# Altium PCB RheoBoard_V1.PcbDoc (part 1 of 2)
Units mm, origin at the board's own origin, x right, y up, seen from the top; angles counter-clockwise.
Board outline 146 x 88.34 mm, 2 copper layers (Top Layer, Bottom Layer); 132 components, 71 nets, 340 pads, 144 vias.
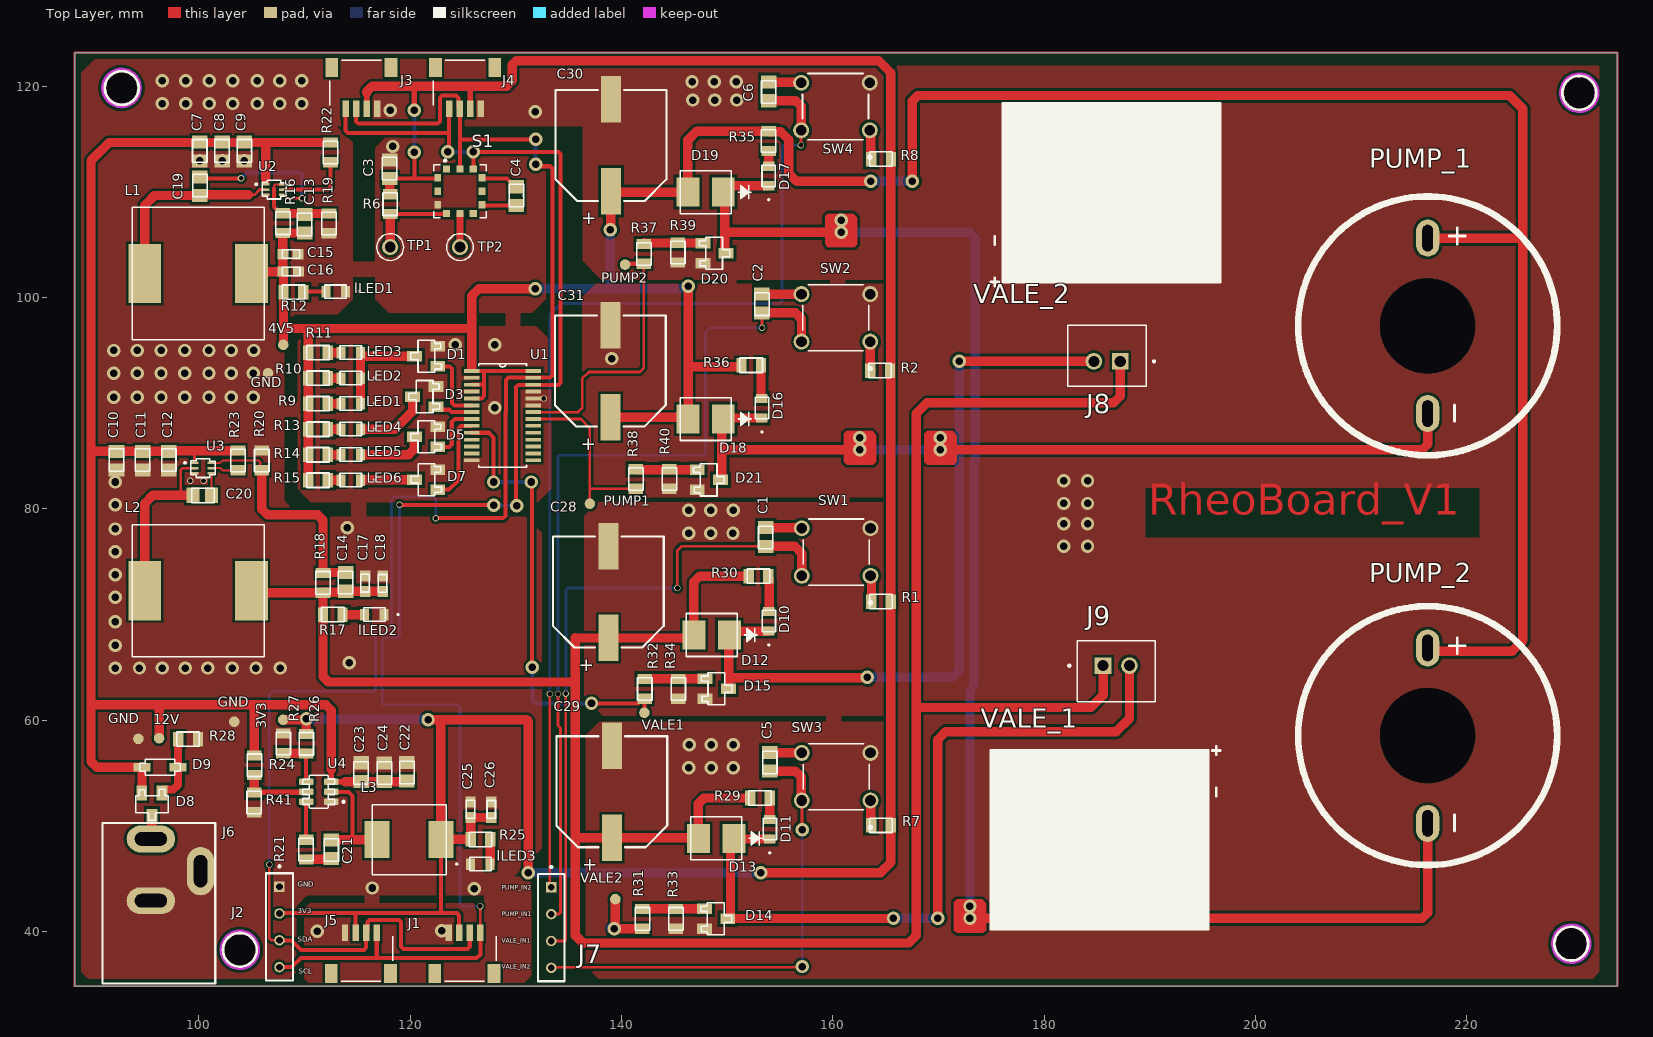
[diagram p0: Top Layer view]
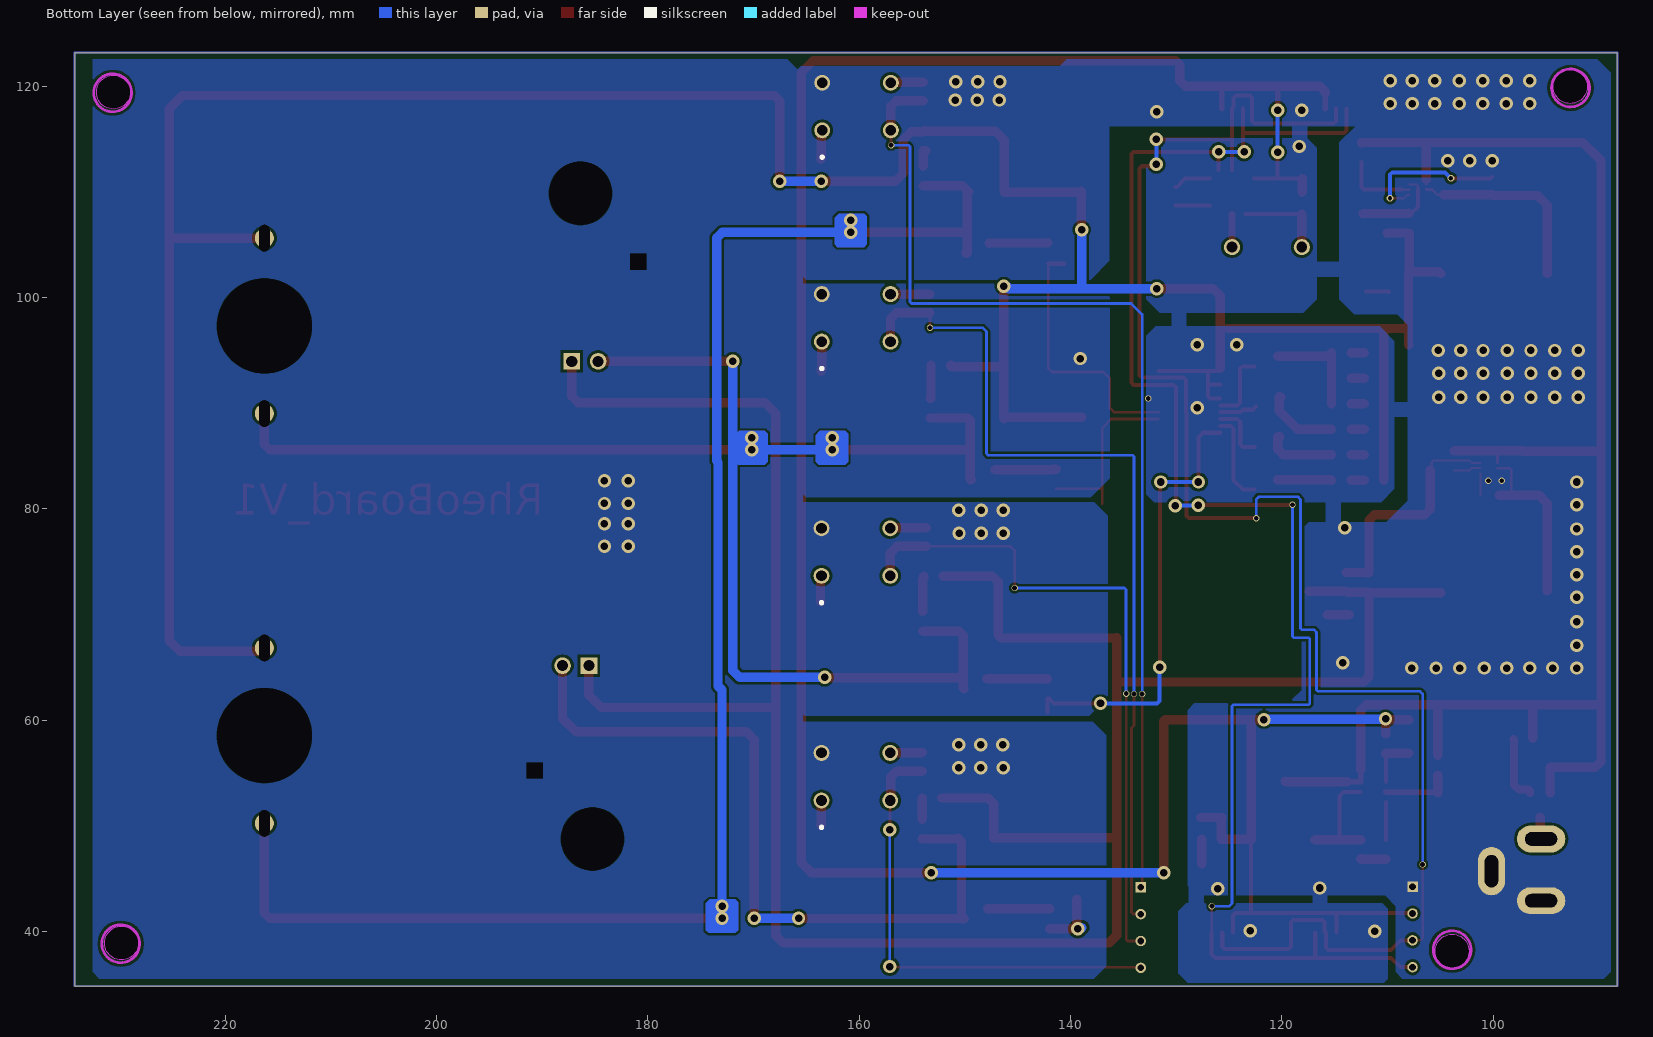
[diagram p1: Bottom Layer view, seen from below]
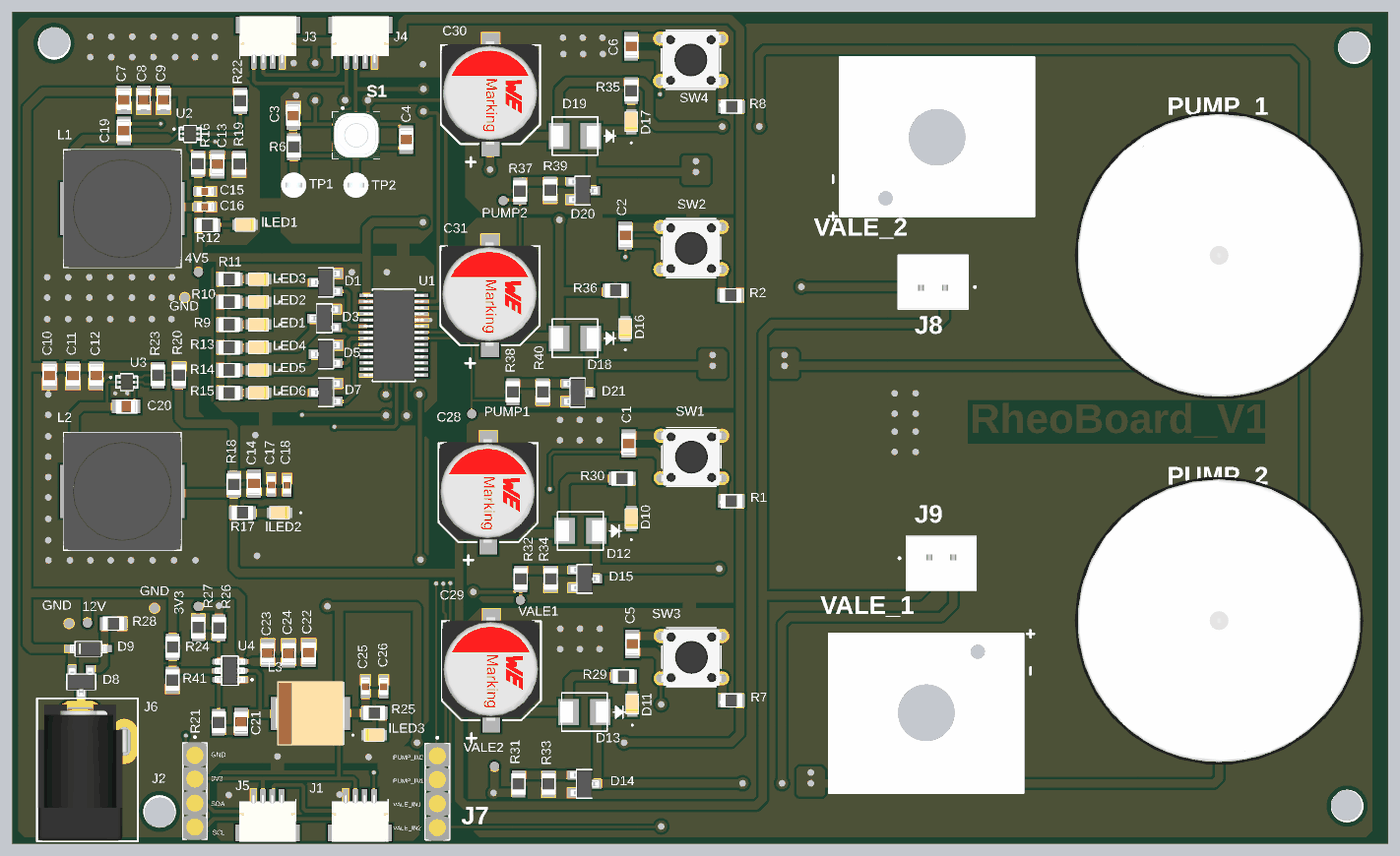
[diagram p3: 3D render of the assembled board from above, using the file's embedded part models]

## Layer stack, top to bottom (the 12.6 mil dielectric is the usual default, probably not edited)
Top Solder: solder mask 0.0102, Solder Resist, Dk 3.5
Top Layer: signal copper 0.0356
Dielectric 1: dielectric 0.32, FR-4, Dk 4.8
Bottom Layer: signal copper 0.0356
Bottom Solder: solder mask 0.0102, Solder Resist, Dk 3.5

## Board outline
88.24,34.85 88.24,123.19 106.965,123.19 234.244,123.19 234.244,34.85
cut-out: 228.201,38.92 ccw(c229.801,38.92) 229.801,37.32 ccw(c229.801,38.92) 231.401,38.92 ccw(c229.801,38.92) 229.801,40.52 ccw(c229.801,38.92)
cut-out: 228.201,38.92 ccw(c229.801,38.92) 229.801,37.32 ccw(c229.801,38.92) 231.401,38.92 ccw(c229.801,38.92) 229.801,40.52 ccw(c229.801,38.92)
cut-out: 228.963,119.438 ccw(c230.563,119.438) 230.563,117.838 ccw(c230.563,119.438) 232.163,119.438 ccw(c230.563,119.438) 230.563,121.038 ccw(c230.563,119.438)
cut-out: 228.963,119.438 ccw(c230.563,119.438) 230.563,117.838 ccw(c230.563,119.438) 232.163,119.438 ccw(c230.563,119.438) 230.563,121.038 ccw(c230.563,119.438)
cut-out: 91.11,119.957 ccw(c92.71,119.957) 92.71,118.357 ccw(c92.71,119.957) 94.31,119.957 ccw(c92.71,119.957) 92.71,121.557 ccw(c92.71,119.957)
cut-out: 102.286,38.158 ccw(c103.886,38.158) 103.886,36.558 ccw(c103.886,38.158) 105.486,38.158 ccw(c103.886,38.158) 103.886,39.758 ccw(c103.886,38.158)

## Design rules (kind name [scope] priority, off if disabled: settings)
Clearance [All] p1: gap=0.254 ignorepadtopadclearanceinfootprint=FALSE except(0: Arc-Hole Track-Hole SMDPad-Hole THPad-Hole Via-Hole Fill-Hole Poly-Hole Region-Hole Text-Hole)
PolygonConnect [All] p1: connectstyle=Direct reliefconductorwidth=0.254 reliefentries=4 polygonreliefangle="90 Angle" airgapwidth=0.254
RoutingVias [All] p1: holewidth=0.45 width=0.55 viastyle="Through Hole" minholewidth=0.381 minwidth=0.381 maxholewidth=1.27 maxwidth=1.27
SolderMaskExpansion [All] p1: expansion=0.102 istentingtop=FALSE
Width [All] p1: maxlimit=0.889 minlimit=0.203 preferedwidth=0.381 minimp=50.000000 maximp=50.000000 favimp=50.000000
30 further rules are at their usual default settings.

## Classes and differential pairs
component class POWER: 3V3 4V5 12V C7 C8 C9 C10 C11 C12 C13 C14 C15 C16 C17 C18 C19 C20 C21 C22 C23 C24 C25 C26 D8 D9 GND J6 L1 L2 L3 lLED1 lLED2 lLED3 R12 R16 R17 R18 R19 R20 R21 R22 R23 R24 R25 R26 R27 R28 R41 U2 U3 U4
component class MAIN: C1 C2 C3 C4 C5 C6 C28 C29 C30 C31 D1 D3 D5 D7 D10 D11 D12 D13 D14 D15 D16 D17 D18 D19 D20 D21 J1 J2 J3 J4 J5 J7 J8 J9 LED1 LED2 LED3 LED4 LED5 LED6 PUMP1 PUMP2 PUMP_1 PUMP_2 R1 R2 R6 R7 R8 R9 R10 R11 R13 R14 R15 R29 R30 R31 R32 R33 R34 R35 R36 R37 R38 R39 R40 S1 SW1 SW2 SW3 SW4 TP1 TP2 U1 VALE1 VALE2 VALE_1 VALE_2

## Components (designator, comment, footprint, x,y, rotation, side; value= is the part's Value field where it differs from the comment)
3V3 "TP_1MM" TP_1mm 107.975,60.046 r90 top
4V5 "TP_1MM" TP_1mm 108.001,95.529 r90 top
12V "TP_1MM" TP_1mm 96.241,58.293 r90 top
C1 "0.1UF,50V" CAP_CER_0805 153.64,77.35 r270 top
C2 "0.1UF,50V" CAP_CER_0805 153.289,99.441 r270 top
C3 "0.1UF,50V" CAP_CER_0805 118.06,112.15 r90 top
C4 "1nF 50V" CAP_CER_0805 130.048,109.601 r90 top
C5 "0.1UF,50V" CAP_CER_0805 154.035,56.07 r270 top
C6 "0.1UF,50V" CAP_CER_0805 153.924,119.507 r270 top
C7 "10UF 50V" CAP_CER_0805 100.09,113.824 r90 top
C8 "10UF 50V" CAP_CER_0805 102.2,113.824 r90 top
C9 "0.1UF,50V" CAP_CER_0805 104.31,113.824 r90 top
C10 "10UF 50V" CAP_CER_0805 92.212,84.564 r90 top
C11 "10UF 50V" CAP_CER_0805 94.688,84.564 r90 top
C12 "0.1UF,50V" CAP_CER_0805 97.165,84.564 r90 top
C13 "18pF 50V" CAP_CER_0805 110.01,106.99 r270 top
C14 "18pF 50V" CAP_CER_0805 113.896,73.1 r270 top
C15 "22uF 6.3V" CAP_CER_0603 108.68,104.11 r180 top
C16 "22uF 6.3V" CAP_CER_0603 108.69,102.46 r180 top
C17 "22uF 6.3V" CAP_CER_0603 115.74,72.93 r270 top
C18 "22uF 6.3V" CAP_CER_0603 117.4,72.91 r270 top
C19 "0.1UF,50V" CAP_CER_0805 100.1,110.54 r90 top
C20 "0.1UF,50V" CAP_CER_0805 100.33,81.28 r0 top
C21 "0.1UF,50V" CAP_CER_0805 112.54,47.8 r270 top
C22 "0.1UF,50V" CAP_CER_0805 119.699,55.136 r270 top
C23 "10UF 25V" CAP_CER_0805 115.36,55.095 r270 top
C24 "10UF 25V" CAP_CER_0805 117.569,55.076 r270 top
C25 "22uF 6.3V" CAP_CER_0603 125.72,51.53 r270 top
C26 "22uF 6.3V" CAP_CER_0603 127.671,51.525 r270 top
C28 "100uF 25V" CAP_ALUM_SMD_D10_H12.4 138.75,72.14 r270 top
C29 "100uF 25V" CAP_ALUM_SMD_D10_H12.4 139.08,53.24 r270 top
C30 "100uF 25V" CAP_ALUM_SMD_D10_H12.4 139,114.395 r270 top
C31 "100uF 25V" CAP_ALUM_SMD_D10_H12.4 138.94,93.04 r270 top
D1 "30V 5.8A" SOT-23-3 121.505,94.445 r90 top
D3 "30V 5.8A" SOT-23-3 121.335,90.635 r90 top
D5 "30V 5.8A" SOT-23-3 121.505,86.825 r90 top
D7 "30V 5.8A" SOT-23-3 121.51,82.77 r90 top
D8 "20V 4A" SOT-23-3 95.57,52.02 r180 top
D9 "BZT52C5V1" SOD-123 96.33,55.56 r0 top
D10 "Led green" "LED_LS R976_AOS" 153.94,69.38 r90 top
D11 "Led green" "LED_LS R976_AOS" 154.03,49.7 r90 top
D12 "3A 40V" DO214AA 148.53,68.07 r180 top
D13 "3A 40V" DO214AA 148.955,48.835 r180 top
D14 "30V 5.8A" SOT-23-3 148.955,41.215 r270 top
D15 "30V 5.8A" SOT-23-3 149.01,62.99 r270 top
D16 "Led green" "LED_LS R976_AOS" 153.289,89.535 r90 top
D17 "Led green" "LED_LS R976_AOS" 153.924,111.506 r90 top
D18 "3A 40V" DO214AA 147.954,88.508 r180 top
D19 "3A 40V" DO214AA 147.954,109.982 r180 top
D20 "30V 5.8A" SOT-23-3 148.798,104.196 r270 top
D21 "30V 5.8A" SOT-23-3 148.273,82.748 r270 top
GND "TP_1MM" TP_1mm 103.353,59.868 r90 top
GND "TP_1MM" TP_1mm 94.285,58.242 r90 top
GND "TP_1MM" TP_1mm 106.553,92.837 r90 top
J1 "14417" SPARKFUN_PRT-14417 125.14,37.453 r0 top
J2 "TS-104-T-A" HDR_THT_1X04_P2.54 107.63,40.45 r270 top
J3 "14417" SPARKFUN_PRT-14417 115.39,120.33 r180 top
J4 "14417" SPARKFUN_PRT-14417 125.19,120.33 r180 top
J5 "14417" SPARKFUN_PRT-14417 115.34,37.453 r0 top
J6 "694106301002" "CONN PWR JACK 2.1X5.5MM SOLDER" 95.72,42.93 r90 top
J7 "TS-104-T-A" HDR_THT_1x04_P2.54 133.35,40.386 r270 top
J8 "VERT" CONN_SMD_TOP_P2.50 185.941,94.488 r0 top
J9 "VERT" CONN_SMD_TOP_P2.50 186.817,64.643 r180 top
L1 "2.2uH" IND_12.5x12.5_H8.5 99.93,102.28 r180 top
L2 "2.2uH" IND_12.5x12.5_H8.5 99.93,72.263 r180 top
L3 "4.7uH" IND_6.8X6.5_H2.8 123.42,52 r180 top
LED1 "RED 2V 20mA" "LED_LS R976_AOS" 114.381,89.965 r180 top
LED2 "RED 2V 20mA" "LED_LS R976_AOS" 114.381,92.378 r180 top
LED3 "RED 2V 20mA" "LED_LS R976_AOS" 114.381,94.791 r180 top
LED4 "Led green" "LED_LS R976_AOS" 114.381,87.552 r180 top
LED5 "Led green" "LED_LS R976_AOS" 114.381,85.139 r180 top
LED6 "Led green" "LED_LS R976_AOS" 114.381,82.726 r180 top
lLED1 "RED 2V 20mA" "LED_LS R976_AOS" 112.95,100.56 r180 top
lLED2 "RED 2V 20mA" "LED_LS R976_AOS" 116.62,70 r180 top
lLED3 "RED 2V 20mA" "LED_LS R976_AOS" 126.65,46.4 r0 top
PUMP1 "TP_1MM" TP_1mm 137.008,80.493 r90 top
PUMP2 "TP_1MM" TP_1mm 140.335,103.124 r90 top
PUMP_1 "0010844022" "PUMP_LPM - ZR370-02PM" 216.281,97.327 r270 top
PUMP_2 "0010844022" "PUMP_LPM - ZR370-02PM" 216.281,58.547 r270 top
R1 "10K 1% 0805" RES_0805 164.55,71.23 r0 top
R2 "10K 1% 0805" RES_0805 164.465,93.091 r0 top
R6 "10K 1% 0805" RES_0805 118.11,108.839 r90 top
R7 "10K 1% 0805" RES_0805 164.55,50.07 r0 top
R8 "10K 1% 0805" RES_0805 164.564,113.106 r0 top
R9 "220R 0805" RES_0805 111.279,89.959 r180 top
R10 "220R 0805" RES_0805 111.279,92.372 r180 top
R11 "220R 0805" RES_0805 111.279,94.785 r180 top
R12 "1K 1% 0805" RES_0805 108.95,100.51 r180 top
R13 "220R 0805" RES_0805 111.279,87.546 r0 top
R14 "220R 0805" RES_0805 111.279,85.133 r0 top
R15 "220R 0805" RES_0805 111.279,82.72 r0 top
R16 "130K 0805" RES_0805 107.96,107.04 r270 top
R17 "1K 1% 0805" RES_0805 112.68,70 r180 top
R18 "270K 0805" RES_0805 111.754,73.01 r270 top
R19 "20K 0805" RES_0805 112.32,107.02 r270 top
R20 "30K 0805" RES_0805 105.96,84.6 r270 top
R21 "30Ohm 0805" RES_0805 110.15,47.76 r270 top
R22 "100K 0805" RES_0805 112.46,113.74 r90 top
R23 "100K 0805" RES_0805 103.71,84.6 r90 top
R24 "174K 0805" RES_0805 105.26,55.75 r90 top
R25 "470R 0805" RES_0805 126.655,48.731 r180 top
R26 "75K 0805" RES_0805 110.169,57.779 r90 top
R27 "24K 0805" RES_0805 108,57.81 r270 top
R28 "100K 0805" RES_0805 98.99,58.21 r180 top
R29 "220R 0805" RES_0805 153.105,52.645 r0 top
R30 "220R 0805" RES_0805 152.96,73.64 r0 top
R31 "100R 0805" RES_0805 141.97,41.215 r90 top
R32 "100R 0805" RES_0805 142.195,62.97 r90 top
R33 "10K 1% 0805" RES_0805 145.145,41.215 r90 top
R34 "10K 1% 0805" RES_0805 145.37,62.97 r90 top
R35 "220R 0805" RES_0805 153.924,114.808 r270 top
R36 "220R 0805" RES_0805 152.273,93.599 r0 top
R37 "100R 0805" RES_0805 142.113,104.14 r90 top
R38 "100R 0805" RES_0805 141.361,82.831 r90 top
R39 "10K 1% 0805" RES_0805 145.322,104.25 r90 top
R40 "10K 1% 0805" RES_0805 144.536,82.831 r90 top
R41 "36.5K 0805" RES_0805 105.239,52.233 r90 top
S1 "MPRLS0025PA00001A" XDCR_MPRLS0025PA00001A 124.714,110.061 r0 top
SW1 "B3F-1020" SW_B3F-1000_OMR 163.56,73.67 r180 top
SW2 "B3F-1020" SW_B3F-1000_OMR 163.531,95.832 r180 top
SW3 "B3F-1020" SW_B3F-1000_OMR 163.56,52.415 r180 top
SW4 "B3F-1020" SW_B3F-1000_OMR 163.498,115.826 r180 top
TP1 "5002" KEYSTONE_5002 118.11,104.775 r0 top
TP2 "5002" KEYSTONE_5002 124.714,104.775 r0 top
U1 "PCA9685PW,118" TSSOP-28 128.745,88.835 r0 top
U2 "TPS563203DRLR" SOT-563 107.13,110.22 r0 top
U3 "TPS563203DRLR" SOT-563 100.4,83.86 r0 top
U4 "TPS56339DDCT" SOT-23-6 111.35,53.235 r180 top
VALE1 "TP_1MM" TP_1mm 142.164,60.719 r90 top
VALE2 "TP_1MM" TP_1mm 139.421,43.078 r90 top
VALE_1 "0010844022" VALE_FA0520E 185.226,48.768 r270 top
VALE_2 "0010844022" VALE_FA0520E 186.369,109.855 r90 top

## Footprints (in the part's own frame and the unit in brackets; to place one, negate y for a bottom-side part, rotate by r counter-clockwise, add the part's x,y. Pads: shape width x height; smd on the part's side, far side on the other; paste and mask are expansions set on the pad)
CAP_ALUM_SMD_D10_H12.4 [mm]
  rect 4.4x1.9 smd: 1(4.35,0) 2(-4.35,0)
  silkscreen extent -5.25,-5.25 5.25,5.25, body extent -5.67,-5.21 5.33,5.09, height 12.25
CAP_CER_0603 [mm]
  rect 1.04x0.97 smd paste+0 mask+0.102: 1(-0.726,0) 2(0.726,0)
  silkscreen extent -0.89,-0.4 0.79,0.4, body extent -0.8,-0.4 0.8,0.4, height 0.95
CAP_CER_0805 [mm]
  rect 1.24x1.47 smd: 1(-0.885,0) 2(0.885,0)
  silkscreen extent -1,-0.68 1.13,0.68, body extent -1,-0.62 1,0.63, height 1.45
"CONN PWR JACK 2.1X5.5MM SOLDER" [mil]
  oval 100x180 hole 50 slot 120 at 90 deg: 1(230,10) 2(0,10)
  oval 180x100 hole 50 slot 120 at 0 deg: 3(110,-175)
  silkscreen extent -308,-230 290,190, body extent -306,-187 265,187, height 421
CONN_SMD_TOP_P2.50 [mm]
  rect 1.575x1.575 / inner round 1.575 / far side rect 1.575x1.575 hole 1.05: 1(1.25,-0.525)
  round 1.575 hole 1.05: 2(-1.25,-0.525)
  silkscreen extent -3.7,-2.88 4.54,2.88, body extent -3.75,-2.79 3.75,2.91, height 2.11
DO214AA [mil]
  rect 85x108 smd paste+0 mask+0: 1(-66,0) 2(66,0)
  silkscreen extent -170,-80 95,80, body extent -108,-78 108,78, height 96
HDR_THT_1X04_P2.54 [mm]
  rect 0.985x0.985 hole 0.635: 01(-3.81,0)
  round 0.985 hole 0.635: 02(-1.27,0) 03(1.27,0) 04(3.81,0)
  silkscreen extent -5.83,-1.27 5.08,1.27, body extent -5.18,-1.27 5.18,1.27, height 8.28
HDR_THT_1x04_P2.54 [mm]
  rect 0.985x0.985 hole 0.635: 01(-3.81,0)
  round 0.985 hole 0.635: 02(-1.27,0) 03(1.27,0) 04(3.81,0)
  silkscreen extent -5.83,-1.27 5.08,1.27, body extent -5.18,-1.27 5.18,1.27, height 8.28
IND_6.8X6.5_H2.8 [mm]
  rect 2.35x3.5 smd: 1(6.55,3.3) 2(0.5,3.3)
  silkscreen extent 0,0 7,6.6, body extent -0.09,-0.1 7.2,6.71, height 3.05
IND_12.5x12.5_H8.5 [mm]
  rect 3.1x5.6 smd: 1(-5.05,0) 2(5.05,0)
  silkscreen extent -6.25,-6.25 6.25,6.25, body extent -6.25,-6.25 6.25,6.25, height 6.5
KEYSTONE_5002 [mm]
  round 1.53 hole 1.02: TP(0,0)
  silkscreen extent -1.27,-1.27 1.27,1.27, body extent -1.27,-1.27 1.27,1.27, height 4.57
"LED_LS R976_AOS" [mil]
  rect 33.78x43 smd paste+0 mask+0: 1(-36.39,0) 2(36.39,0)
  silkscreen extent -91,-25 40,25, body extent -39,-26 39,26, height 32
"PUMP_LPM - ZR370-02PM" [mm]
  oval 3.5x2.2 / inner round 1.524 / far side round 1.808 hole 1 slot 2.5 at 0 deg paste-2539.97 mask+0: 1(-8.3,0) 2(8.3,0)
  round 1.524 hole 9 unplated: 3(0,0)
  silkscreen extent -12.25,-12.25 12.25,12.25, body extent -15.31,-15.31 15.31,15.31, height 65
RES_0805 [mm]
  rect 0.97x1.38 smd: 1(-0.93,0) 2(0.93,0)
  silkscreen extent -1.07,-0.69 1.07,0.68, body extent -1,-0.62 1,0.63, height 0.6
SOD-123 [mm]
  rect 1.6x0.8 smd: 1(-1.7,0) 2(1.7,0)
  silkscreen extent -1.91,-0.76 1.91,0.76, body extent -1.82,-0.77 1.83,0.78, height 1.44
SOT-23-3 [mm]
  rect 1x1.4 smd paste+0 mask+0.102: 1(-0.95,-1.1) 2(0.95,-1.1) 3(0,1.1)
  silkscreen extent -1.52,-1.46 1.52,1.46, body extent -1.45,-1.4 1.45,1.4, height 1.25
SOT-23-6 [mm]
  rrect25% 1.35x0.6 smd: 1(-1.185,0.95) 2(-1.185,0) 3(-1.185,-0.95) 4(1.185,-0.95) 5(1.185,0) 6(1.185,0.95)
  silkscreen extent -2.45,-1.55 1.52,1.55, body extent -1.4,-1.5 1.4,1.5, height 1.16
SOT-563 [mil]
  rect 28x9 smd paste+0 mask+0: 1(-31.5,19.69) 2(-31.5,0) 3(-31.5,-19.69) 4(31.5,-19.69) 5(31.5,0) 6(31.5,19.69)
  silkscreen extent -71,-35 45,35, body extent -34,-34 34,34, height 24
SPARKFUN_PRT-14417 [mm]
  rect 0.6x1.55 smd: 1(-1.5,2.45) 2(-0.5,2.45) 3(0.5,2.45) 4(1.5,2.45)
  rect 1.2x1.8 smd: S1(-2.8,-1.425) S2(2.8,-1.425)
  silkscreen extent -1.88,-2.12 3,2.12, body extent -3,-2.37 3,2.58, height 2.95
SW_B3F-1000_OMR [mm]
  round 1.508 / inner round 1.524 / far side round 1.508 hole 1 paste-2539.97 mask+0: 1(0,0) 2(6.5,0) 3(0,-4.5) 4(6.5,-4.5)
  silkscreen extent -0.13,-5.38 6.38,2.67, body extent -0.7,-5.24 7.2,0.76, height 5
TP_1mm [mm]
  round 1 smd: 1(0,0)
TSSOP-28 [mil]
  rect 58x14 smd: 1(-115,166) 2(-115,141) 3(-115,115) 4(-115,90) 5(-115,64) 6(-115,38) 7(-115,13) 8(-115,-13) 9(-115,-38) 10(-115,-64) 11(-115,-90) 12(-115,-115) 13(-115,-141) 14(-115,-166) 15(115,-166) 16(115,-141) 17(115,-115) 18(115,-90) 19(115,-64) 20(115,-38) 21(115,-13) 22(115,13) 23(115,38) 24(115,64) 25(115,90) 26(115,115) 27(115,141) 28(115,166)
  silkscreen extent -89,-193 89,193, body extent -126,-191 126,191, height 43
VALE_FA0520E [mm]
  rect 1x0.8 hole 1.5 square unplated: 4(-6.477,5.461)
  rect 1.5x0.8 hole 6 unplated: 4(0,0)
  silkscreen extent -8.76,-10.29 8.51,11.43, body extent -8.1,-10 18,10, height 55.19
XDCR_MPRLS0025PA00001A [mm]
  rect 0.7x0.65 smd: 1(-1.27,2.1) 2(0,2.1) 3(1.27,2.1) 7(1.27,-2.1) 8(0,-2.1) 9(-1.27,-2.1)
  rect 0.65x0.7 smd: 4(2.1,1.27) 5(2.1,0) 6(2.1,-1.27) 10(-2.1,-1.27) 11(-2.1,0) 12(-2.1,1.27)
  silkscreen extent -2.5,-2.5 2.5,3, body extent -2.46,-2.5 2.54,2.5, height 5.9

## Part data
C1 C2 C3 C5 C6 C9 C12 C19 C20 C21 C22: library part "CAP_CER, 0805, X7R, 0.1UF, 5%, 50V", "Ceramic Capacitor, Multilayer, Ceramic, 50V, 10% +Tol, 10% -Tol, X7R, 15% TC, 0.1uF, Surface Mount, 0805", Capacitance=100nF, Dielectric Material=Ceramic, Manufacturer=Nextgen, Manufacturer Part Number=0805B104K500BD, Max Operating Temperature=125°C, Min Operating Temperature=-55°C, Supplier Part Number 1=3372-0805B104K500BDTR-ND, Voltage Rating (DC)=50V
C4: library part "CAP_CER 0805 1NF 50V ULTRA STABL", "Cap Ceramic 0.001uF 50V X8R 10% Pad SMD 0805 150C T/R Automotive AEC-Q200", Capacitance=1nF, Case/Package=0805, Dielectric=X8R, Dielectric Material=Ceramic, Manufacturer="Yageo Group", Manufacturer Part Number=C0805C102K5HACAUTO, Max Operating Temperature=150°C, Min Operating Temperature=-55°C, Ratings=AEC-Q200, Supplier Part Number 1=399-C0805C102K5HACAUTODKR-ND, Temperature Coefficient=30ppm/°C, Voltage Rating=50V
C7 C8 C10 C11: library part "CAP_CER, 0805, X5R, 10UF, 10%, 50V", "CAP_CER,0805,X5R,10UF,10%,50V", Manufacturer=Nextgen, Manufacturer Part Number=0805W106K500CC, Supplier Part Number 1=3372-0805W106K500CCTR-ND
C13 C14: library part "CAP_CER, 18PF 50V X8R 0805", "Multilayer Ceramic Capacitors MLCC - SMD/SMT 50V 18pF X8R 0805 5%", Capacitance=18pF, Case/Package=0805, Dielectric=X8R, Dielectric Material=Ceramic, Manufacturer="Yageo Group", Manufacturer Part Number=C0805C180J5HACTU, Max Operating Temperature=150°C, Min Operating Temperature=-55°C, Supplier Part Number 1=399-C0805C180J5HACTUCT-ND, Temperature Coefficient=30ppm/°C, Voltage Rating=50V
C15 C16 C17 C18 C25 C26: library part "CAP_CER 22UF 6.3V X6S 0603", "6.3V 22uF X6S ±20% 0603 Multilayer Ceramic Capacitors MLCC - SMD/SMT ROHS", Capacitance=22µF, Case Code (Imperial)=0603, Case Code (Metric)=1608, Dielectric=X6S, Dielectric Material=Ceramic, Manufacturer=Murata, Manufacturer Lifecycle Status="IN PRODUCTION", Manufacturer Part Number=GRM188C80J226ME15D, Max Operating Temperature=105°C, Min Operating Temperature=-55°C, Supplier Part Number 1=490-10471-1-ND, Tolerance=20%, Voltage Rating=6.3V
C23 C24: library part "CAP_CER, 0805, X5R, 10UF, 10%, 25V", "Cap SMD, 0805, X5R, 10UF, 10%, 25V", Manufacturer=Nextgen, Manufacturer Part Number=0805W106K250CC, Supplier Part Number 1=3372-0805W106K250CCTR-ND
C28 C29 C30 C31: library part "CAP ALUM POLY 100UF 20% 25V SMD", "WCAP-PSLC Aluminum Polymer Capacitors", Capacitance=100µF, Case/Package=Radial, ESR (Equivalent Series Resistance)=15mΩ, Leakage Current=500µA, Manufacturer="Wurth Elektronik", Manufacturer Lifecycle Status=ACTIVE, Manufacturer Part Number=875075561005, Max Operating Temperature=105°C, Min Operating Temperature=-55°C, Ripple Current=4.8A, Supplier Part Number 1=732-6499-6-ND, Tolerance=20%, Voltage Rating=25V
D1 D3 D5 D7 D14 D15 D20 D21: library part "MOSFET N-CH 30V 5.8A SOT23-3", "Trans MOSFET N-CH 30V 5.7A 3-Pin SOT-23", Case/Package=SOT-23, Continuous Drain Current (ID)=5.7A, Drain to Source Breakdown Voltage=30V, Drain to Source Resistance=26.5mΩ, Gate to Source Voltage (Vgs)=12V, Input Capacitance=630pF, Manufacturer="Alpha & Omega Semiconductor", Manufacturer Part Number=AO3400A, Max Junction Temperature (Tj)=150°C, Max Power Dissipation=1.4W, Min Operating Temperature=-55°C, Supplier Part Number 1=785-1000-2-ND, Threshold Voltage=650mV
D8: library part "MOSFET P-CH 20V 4A SOT23-3", "P-ch Mosfet 20V 4A 39MΩ@4A, 4.5V 9.1NC@4.5V 294PF@10V SOT-23-3 SMD 2.9MM × 1.3MM × 1.03MM", Case/Package=SOT-23, Continuous Drain Current (ID)=4A, Drain to Source Breakdown Voltage=-20V, Drain to Source Resistance=42.5mΩ, Gate to Source Voltage (Vgs)=8V, Input Capacitance=294pF, Manufacturer="Diodes Inc.", Manufacturer Part Number=DMG3415U-7, Max Junction Temperature (Tj)=150°C, Max Power Dissipation=900mW, Min Breakdown Voltage=20V, Min Operating Temperature=-55°C, Supplier Part Number 1=DMG3415UDIDKR-ND, Threshold Voltage=-550mV
D9: library part "DIODE ZENER 5.1V 500MW SOD123F", "BZT52C5V1 Series 500 mW 5.1 V 10 mA Surface Mount Zener Diode - SOD-123", Current=1A, Forward Current=10mA, Forward Voltage=900mV, Manufacturer="Diodes Inc.", Manufacturer Part Number=BZT52C5V1-7-F, Max Junction Temperature (Tj)=150°C, Max Power Dissipation=370mW, Max Reverse Leakage Current=2µA, Min Operating Temperature=-65°C, Output Current=50mA, Power Rating=500mW, Reference Voltage=5.1V, Reverse Standoff Voltage=2V, Supplier Part Number 1=BZT52C5V1-FDICT-ND, Test Current=5mA, Tolerance=6%, Voltage Tolerance=5.88%
D10 D11 D16 D17 LED4 LED5 LED6: library part "LED GREEN CLEAR CHIP SMD", "Single-color LEDs; LITEON; LTST-C190GKT; Green; 130 °; 2.1 V; 0603", Case Code (Imperial)=0603, Case Code (Metric)=1608, Color=Green, Current=1A, Forward Current=30mA, Forward Voltage=2.6V, Lens Color="Clear, Colorless", Manufacturer="Diodes Inc.", Manufacturer Part Number=LTST-C190GKT, Max Operating Temperature=85°C, Min Operating Temperature=-55°C, Power Dissipation=100mW, Reverse Voltage=5V, Supplier Part Number=160-LTST-C190GKTDKR-ND, Test Current=10mA, Voltage=2V
D12 D13 D18 D19: library part "DIODE SCHOTTKY 40V 3A DO214AB", "Rectifier Diode, Schottky, 1 Phase, 1 Element, 3A, 40V V(RRM), Silicon, DO-214AB", Average Rectified Current=3A, Case/Package=SMC, Forward Voltage=500mV, Manufacturer=onsemi, Manufacturer Lifecycle Status=ACTIVE, Manufacturer Part Number=SS34, Max Forward Surge Current (Ifsm)=100A, Max Junction Temperature (Tj)=150°C, Max Power Dissipation=2.27W, Max Repetitive Reverse Voltage (Vrrm)=40V, Max Reverse Leakage Current=500µA, Min Operating Temperature=-55°C, Peak Reverse Current=20mA, Supplier Part Number 1=SS34FSCT-ND
J1 J3 J4 J5: library part "QWIIC CONNECTOR SMD 4-PIN", "Qwiic Connector SMD 4-PIN", Manufacturer=SparkFun, Supplier Part Number 1=1568-14417-ND
J2 J7: library part "CONN HEADER VERT 4POS 2.54MM", "Samtec 2.54mmpitch4pSingle row pin header, TSseries, right angle, Through hole mounting", Color=Black, Manufacturer=Samtec, Manufacturer Lifecycle Status=PRODUCTION, Supplier Part Number 1=612-TS-104-T-A-ND
J6: library part "CONN PWR JACK 2.1X5.5MM SOLDER", "DC Power Jack Connector WR-DC, Male, Right Angled, THT, 5 A, 24 V", Color=Black, Current Rating=5A, Flammability Rating="UL94 V-0", Insulation Resistance=100MΩ, Manufacturer="Wurth Elektronik", Manufacturer Lifecycle Status=ACTIVE, Max Operating Temperature=85°C, Min Operating Temperature=-40°C, Operating Supply Voltage=24V, Supplier Part Number 1=732-5930-ND
J8 J9: library part "CONN HEADER VERT 2POS 2.5MM", "Board Connector, 2 Contact(s), 1 Row(s), Male, Straight, Solder Terminal", Contact Resistance=20mΩ, Current Rating=3A, Insulation Resistance=1GΩ, Manufacturer=JST, Manufacturer Part Number=B2B-XH-A, Max Operating Temperature=85°C, Min Operating Temperature=-25°C, Supplier Part Number 1=455-B2B-XH-A-ND
L1 L2: library part "FIXED IND 2.2UH 3A 45 MOHM SMD", "Inductor Power Shielded Wirewound 2.2uH 20% 100KHz Ferrite 3.1A 0.045Ohm DCR 1515 T/R", Case/Package=1515, Current Rating=3A, DC resistance (DCR)=45mΩ, Inductance=2.2µH, Inductance Tolerance=20%, Manufacturer=Vishay, Manufacturer Part Number=IFSC1515AHER2R2M01, Max Current Rating=2.8A, Max Operating Temperature=125°C, Min Operating Temperature=-55°C, Resistance=35mΩ, RMS Current (Irms)=3.1A, Supplier Part Number 1=541-1404-6-ND, Test Frequency=100kHz
L3: library part "FIXED IND 4.7UH 6.3A 33 MOHM SMD", "FIXED IND 4.7UH 6.3A 33MOHM SMD / 4.7 µH Shielded Molded Inductor 6.3 A 33mOhm Max Nonstandard", Case/Package=2826, Current Rating=6.3A, DC resistance (DCR)=33mΩ, Inductance=4.7µH, Manufacturer=Sumida, Manufacturer Part Number=0630CDMCCDS-4R7MC, Max Operating Temperature=125°C, Min Operating Temperature=-55°C, Saturation Current=6.8A, Supplier Part Number 1=308-2466-1-ND, Test Frequency=100kHz, Tolerance=20%
LED1 LED2 LED3 lLED1 lLED2 lLED3: library part "LED RED DIFFUSED 0805 SMD", "Red 633nm LED Indication - Discrete 2V 0805 (2012 Metric)", Manufacturer=Osram, Manufacturer Part Number="LS R976-NR-1-0-20-R18", Supplier Part Number 1=475-LSR976-NR-1CT-ND
PUMP_1 PUMP_2: library part "Air Pump and Vacuum DC Motor - 4.5 V and 2.5 LPM - ZR370-02PM", "Connector Header 2 Position 6.35mm Solder Straight Thru-Hole 2 Terminal 1 Port MLX-Series", Color=Natural, Contact Resistance=3.5mΩ, Current Rating=13.5A, Dielectric Material=Polyester, Flammability Rating="UL94 V-2", Insulation Resistance=1GΩ, Manufacturer=Molex, Manufacturer Lifecycle Status=ACTIVE, Manufacturer Part Number=10-84-4022, Max Operating Temperature=105°C, Min Operating Temperature=-55°C, Operating Force=6.672N, Ratings=CSA, Supplier Part Number 1=WM1263-ND, Voltage Rating=600V
R1 R2 R6 R7 R8 R33 R34 R39 R40: library part "RES_SMD 10K 1% 1/4W 0805", "Res Thick Film 0805 10K Ohm 1% 0.125W(1/8W) ±100ppm/C Pad SMD Automotive T/R", Case Code (Imperial)=0805, Manufacturer=Vishay, Manufacturer Package Identifier=CRCW0805-e3, Manufacturer Part Number=CRCW080510K0FKEA, Max Operating Temperature=155°C, Min Operating Temperature=-55°C, Power Dissipation=125mW, Power Rating=120mW, Resistance=10kΩ, Supplier Part Number 1=541-10.0KCTR-ND, Temperature Coefficient=100ppm/°C, Tolerance=1%, Voltage Rating=150V
R9 R10 R11 R13 R14 R15 R29 R30 R35 R36: library part "RES_SMD 220 OHM 1% 1/8W 0805", "Res Thick Film 0805 220 Ohm 1% 0.125W(1/8W) ±100ppm/C Pad SMD Automotive T/R", Ambient Temperature Range High=70°C, Case/Package=0805, Manufacturer="TE Connectivity", Manufacturer Lifecycle Status=ACTIVE, Manufacturer Part Number=CRGCQ0805F220R, Max Operating Temperature=155°C, Min Operating Temperature=-55°C, Operating Supply Voltage=150V, Power Rating=125mW, Ratings=AEC-Q200, Resistance=220Ω, Supplier Part Number 1=A129741TR-ND, Temperature Coefficient=100ppm/°C, Tolerance=1%
R12 R17: library part "RES_SMD 1K 1% 1/8W 0805", "Yageo RC0805FR-071KL SMD Resistor 0603 1k Ohm ±1% Thick Film", Case Code (Imperial)=0805, Manufacturer="Yageo Group", Manufacturer Part Number=RC0805FR-071KL, Max Operating Temperature=155°C, Max Power Dissipation=125mW, Min Operating Temperature=-55°C, Resistance=1kΩ, Supplier Part Number 1=2421935, Temperature Coefficient=100ppm/°C, Tolerance=1%, Voltage Rating=150V
R16: library part "RES_SMD 130K OHM 1% 1/8W 0805", "Res Thick Film 0805 130K Ohm 1% 0.125W(1/8W) ±100ppm/C Pad SMD T/R", Case Code (Imperial)=0805, Manufacturer="Yageo Group", Manufacturer Part Number=RC0805FR-07130KL, Max Operating Temperature=155°C, Max Power Dissipation=125mW, Min Operating Temperature=-55°C, Resistance=130kΩ, Supplier Part Number 1=311-130KCRDKR-ND, Temperature Coefficient=100ppm/°C, Tolerance=1%, Voltage Rating=150V
R18: library part "RES_SMD 270K OHM 5% 1/8W 0805", "Res Thick Film 0805 270K Ohm 5% 0.125W(1/8W) ±100ppm/C Pad SMD T/R", Case Code (Imperial)=0805, Manufacturer="Yageo Group", Manufacturer Package Identifier="0805 (2012 metric)", Manufacturer Part Number=RC0805JR-07270KL, Max Operating Temperature=155°C, Max Power Dissipation=125mW, Min Operating Temperature=-55°C, Resistance=270kΩ, Supplier Part Number 1=311-270KARTR-ND, Temperature Coefficient=100ppm/°C, Tolerance=5%, Voltage Rating=150V
R19: library part "RES_SMD 20K OHM 1% 1/8W 0805", "Res Thick Film 0805 20K Ohm 1% 1/8W ±100ppm/°C Molded SMD Punched Carrier T/R", Case Code (Imperial)=0805, Manufacturer=Panasonic, Manufacturer Lifecycle Status=ACTIVE, Manufacturer Part Number=ERJ6ENF2002V, Max Operating Temperature=155°C, Max Power Dissipation=125mW, Min Operating Temperature=-55°C, Ratings=AEC-Q200, Resistance=20kΩ, Supplier Part Number 1=P20.0KCTR-ND, Temperature Coefficient=100ppm/°C, Tolerance=1%, Voltage Rating=150V
R20: library part "RES_SMD 30K OHM 1% 1/8W 0805", "Res Thick Film 0805 30K Ohm 1% 0.125W ±100ppm/°C Molded SMD Paper T/R", Case/Package=0805, Manufacturer="Stackpole Electronics", Manufacturer Package Identifier="0805 (2012 metric)", Manufacturer Part Number=RMCF0805FT30K0, Max Operating Temperature=155°C, Max Power Dissipation=125mW, Min Operating Temperature=-55°C, Ratings=AEC-Q200, Resistance=30kΩ, Supplier Part Number 1=RMCF0805FT30K0DKR-ND, Temperature Coefficient=100ppm/°C, Tolerance=1%, Voltage Rating=150V
R21: library part "RES_SMD 30 OHM 1% 1/8W 0805", "Res Thick Film 0805 30 Ohm 1% 0.125W(1/8W) ±100ppm/C Pad SMD T/R", Case Code (Imperial)=0805, Manufacturer="Yageo Group", Manufacturer Package Identifier="0805 (2012 metric)", Manufacturer Part Number=RC0805FR-0730RL, Max Operating Temperature=155°C, Max Power Dissipation=125mW, Min Operating Temperature=-55°C, Resistance=30Ω, Supplier Part Number 1=311-30.0CRCT-ND, Temperature Coefficient=100ppm/°C, Tolerance=1%, Voltage Rating=150V
R22 R23 R28: library part "RES_SMD 100K 1% 1/8W 0805", "125mW Thick Film Resistors 150V ±100ppm/℃ ±1% 100kΩ 0805 Chip Resistor - Surface Mount ROHS", Case Code (Imperial)=0805, Manufacturer="Yageo Group", Manufacturer Part Number=RC0805FR-07100KL, Max Operating Temperature=155°C, Max Power Dissipation=125mW, Min Operating Temperature=-55°C, Resistance=100kΩ, Supplier Part Number 1=311-100KCRTR-ND, Temperature Coefficient=100ppm/°C, Tolerance=1%, Voltage Rating=150V
R24: library part "RES_SMD 174K OHM 1% 1/8W 0805", "Res Thick Film 0805 174K Ohm 1% 0.125W(1/8W) ±100ppm/C Pad SMD T/R Automotive AEC-Q200", Case Code (Imperial)=0805, Manufacturer=Vishay, Manufacturer Package Identifier=CRCW0805-e3, Manufacturer Part Number=CRCW0805174KFKEA, Max Operating Temperature=155°C, Max Power Dissipation=125mW, Min Operating Temperature=-55°C, Ratings=AEC-Q200, Resistance=174kΩ, Supplier Part Number 1=541-174KCDKR-ND, Temperature Coefficient=100ppm/°C, Tolerance=1%, Voltage Rating=150V
R25: library part "RES_SMD 470 OHM 5% 1/8W 0805", "Res Thick Film 0805 470 Ohm 5% 0.125W(1/8W) ±100ppm/C Pad SMD T/R Automotive AEC-Q200", Ambient Temperature Range High=70°C, Case/Package=0805, Manufacturer="TE Connectivity", Manufacturer Lifecycle Status=ACTIVE, Manufacturer Part Number=CRGCQ0805J470R, Max Operating Temperature=155°C, Min Operating Temperature=-55°C, Operating Supply Voltage=150V, Power Rating=125mW, Ratings=AEC-Q200, Resistance=470Ω, Supplier Part Number 1=A130132DKR-ND, Temperature Coefficient=100ppm/°C, Tolerance=5%
R26: library part "RES_SMD 75K OHM 1% 1/8W 0805", "Res Thick Film 0805 75K Ohm 1% 1/8W ±100ppm/°C Molded SMD SMD Paper Tape on Plastic Reel", Case Code (Imperial)=0805, Case Code (Metric)=2012, Manufacturer=Bourns, Manufacturer Part Number=CR0805-FX-7502ELF, Max Operating Temperature=155°C, Min Operating Temperature=-55°C, Power Rating=125mW, Resistance=75kΩ, Supplier Part Number 1=118-CR0805-FX-7502ELFTR-ND, Temperature Coefficient=100ppm/°C, Tolerance=1%, Voltage Rating=150V
R27: library part "RES_SMD 24K OHM 1% 1/8W 0805", "Res Thick Film 0805 24K Ohm 1% 0.125W(1/8W) ±100ppm/C Pad SMD T/R", Case Code (Imperial)=0805, Manufacturer="Yageo Group", Manufacturer Package Identifier="0805 (2012 metric)", Manufacturer Part Number=RC0805FR-0724KL, Max Operating Temperature=155°C, Min Operating Temperature=-55°C, Power Rating=125mW, Resistance=24kΩ, Supplier Part Number 1=311-24.0KCRCT-ND, Temperature Coefficient=100ppm/°C, Tolerance=1%, Voltage Rating=150V
R31 R32 R37 R38: library part "RES_SMD 100 OHM 1% 1/8W 0805", "Resistor Thick Film 0805 100 Ohm 1% 1/8W 100ppm/C Molded SMD Punched Carrier T/R", Case Code (Imperial)=0805, Manufacturer=Panasonic, Manufacturer Lifecycle Status=ACTIVE, Manufacturer Package Identifier="0805 (2012 metric)", Manufacturer Part Number=ERJ6ENF1000V, Max Operating Temperature=155°C, Max Power Dissipation=125mW, Min Operating Temperature=-55°C, Ratings=AEC-Q200, Resistance=100Ω, Supplier Part Number 1=P100CCT-ND, Temperature Coefficient=100ppm/°C, Tolerance=1%, Voltage Rating=150V
R41: library part "RES_SMD 36.5K OHM 1% 1/8W 0805", "Res Thick Film 0805 36.5K Ohm 1% 0.125W ±100ppm/°C Molded SMD Paper T/R", Case Code (Imperial)=0805, Case Code (Metric)=2012, Manufacturer="Stackpole Electronics", Manufacturer Package Identifier="0805 (2012 metric)", Manufacturer Part Number=RMCF0805FT36K5, Max Operating Temperature=155°C, Max Power Dissipation=125mW, Min Operating Temperature=-55°C, Ratings=AEC-Q200, Resistance=36.5kΩ, Supplier Part Number 1=738-RMCF0805FT36K5DKR-ND, Temperature Coefficient=100ppm/°C, Tolerance=1%, Voltage Rating=150V
S1: library part "SENSOR 25PSIA 0.1\" 24BIT", "Board Mount Pressure Sensor -0.3V to 3.9V 0psi to 25psi Absolute 12-Pin T/R", Case/Package=SMD/SMT, Current Rating=1.7mA, Manufacturer=Honeywell, Max Operating Temperature=85°C, Max Supply Voltage=3.6V, Min Operating Temperature=-40°C, Min Supply Voltage=1.8V, Operating Supply Current=33.8µA, Supplier Part Number 1=480-7098-2-ND
SW1 SW2 SW3 SW4: library part "SWITCH TACTILE SPST-NO 0.05A 24V", "Switch Tactile N.O. SPST Flat Round Button PC Pins 0.05A 24VDC 0.98N Thru-Hole Bag", Color=Black, Contact Current Rating=50mA, Contact Resistance=100mΩ, Insulation Resistance=100MΩ, Manufacturer=Omron, Max Operating Temperature=70°C, Max Voltage Rating (DC)=24V, Min Operating Temperature=-25°C, Operating Force=1.27N, Supplier Part Number 1=B3F1020
TP1 TP2: library part "PC TEST POINT MINIATURE WHITE", "Test Point, Mini, Thm, Pc, .300 L, .100 Od, Heat Resistant Nylon 46, White", Color=White, Flammability Rating="UL94 V-0", Manufacturer=Keystone, Supplier Part Number 1=36-5002-ND
U1: library part "IC LED DRVR LIN PWM 25MA 28TSSOP", "PCA9685 Series 5.5V 25 mA 1 MHz 12-bit PWM Fm+I2C-Bus LED Controller - TSSOP-28", Ambient Temperature Range High=85°C, Case/Package=TSSOP, Frequency=25MHz, High Level Output Current=10mA, Low Level Output Current=400A, Manufacturer="NXP Semiconductors", Max Power Dissipation=400mW, Max Supply Voltage=5.5V, Min Operating Temperature=-40°C, Min Supply Voltage=2.3V, Nominal Supply Current=6mA, Nominal Supply Voltage (DC)=3V, Output Current=25mA, Output Voltage=5V, Power Dissipation=400W, Supplier Part Number 1=568-11925-6-ND, Temperature Grade=Industrial
U2 U3: library part "IC REG BUCK ADJ 3A SOT563_1", "4.2-V to 17-V input, 3-A synchronous buck converter in SOT563 6-SOT-5X3 -40 to 125", Manufacturer="Texas Instruments", Manufacturer Lifecycle Status=ACTIVE, Supplier Part Number 1=296-TPS563203DRLRDKR-ND
U4: library part "IC REG BUCK ADJ 3A SOT23", "4.5-V to 24-V input, 3-A output synchronous buck converter 6-SOT-23-THIN -40 to 125", Manufacturer="Texas Instruments", Manufacturer Lifecycle Status=ACTIVE, Supplier Part Number 1=296-53564-1-ND
VALE_1 VALE_2: library part "6V Air Valve with 2-pin JST XH Connector - FA0520E", "Connector Header 2 Position 6.35mm Solder Straight Thru-Hole 2 Terminal 1 Port MLX-Series", Color=Natural, Contact Resistance=3.5mΩ, Current Rating=13.5A, Dielectric Material=Polyester, Flammability Rating="UL94 V-2", Insulation Resistance=1GΩ, Manufacturer=Molex, Manufacturer Lifecycle Status=ACTIVE, Manufacturer Part Number=10-84-4022, Max Operating Temperature=105°C, Min Operating Temperature=-55°C, Operating Force=6.672N, Ratings=CSA, Supplier Part Number 1=WM1263-ND, Voltage Rating=600V

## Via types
v1: diameter 1.27, hole 0.711, Top Layer to Bottom Layer, tented both sides, 129 vias
v2: diameter 0.6, hole 0.45, Top Layer to Bottom Layer, tented both sides, 13 vias
v3: diameter 0.65, hole 0.4, Top Layer to Bottom Layer, tented both sides, 2 vias

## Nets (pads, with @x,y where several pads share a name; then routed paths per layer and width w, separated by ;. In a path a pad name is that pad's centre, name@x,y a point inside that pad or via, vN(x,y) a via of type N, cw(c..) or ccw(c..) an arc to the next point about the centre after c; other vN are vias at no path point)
+12: 12V.1 C7.2 C8.2 C9.2 C10.2 C11.2 C12.2 C22.2 C23.2 C24.2 D8.2 D9.1 R22.2 R23.2 R24.2 U2.1 U3.1 U4.3 | length 151.4
  Top Layer w0.203: U2.1@106.33,110.72 106.33,111.17
  Top Layer w0.254: U3.1@99.6,84.37 99.6,85.27
  Top Layer w0.508: 112.54,55.35 112.535,55.345 U4.3@112.535,54.185 113.835,54.185 113.84,54.18
  Top Layer w0.889: D8.2@94.62,53.12 94.625,53.125 94.625,55.555 D9.1@94.63,55.56 90.34,55.56 89.8,56.1 89.8,61.468 ; 12V.1@96.241,58.293 96.241,61.443 96.266,61.468 ; R23.2@103.71,85.52 97.236,85.52 C12.2@97.165,85.449 C11.2@94.688,85.449 C10.2@92.212,85.449 90.061,85.449 89.8,85.71 ; R24.2@105.26,56.68 105.26,61.329 ; 106.33,111.17 106.33,114.674 ; R22.2@112.46,114.67 112.456,114.674 106.33,114.674 ; 112.54,55.35 112.54,60.947 112.019,61.468 96.266,61.468 ; 113.84,54.18 119.628,54.18 C22.2@119.699,54.251 ; 89.8,61.468 96.266,61.468 ; 89.8,61.468 89.8,85.71 ; 89.8,85.71 89.8,112.96 91.519,114.679 103.57,114.679 103.574,114.674 106.33,114.674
